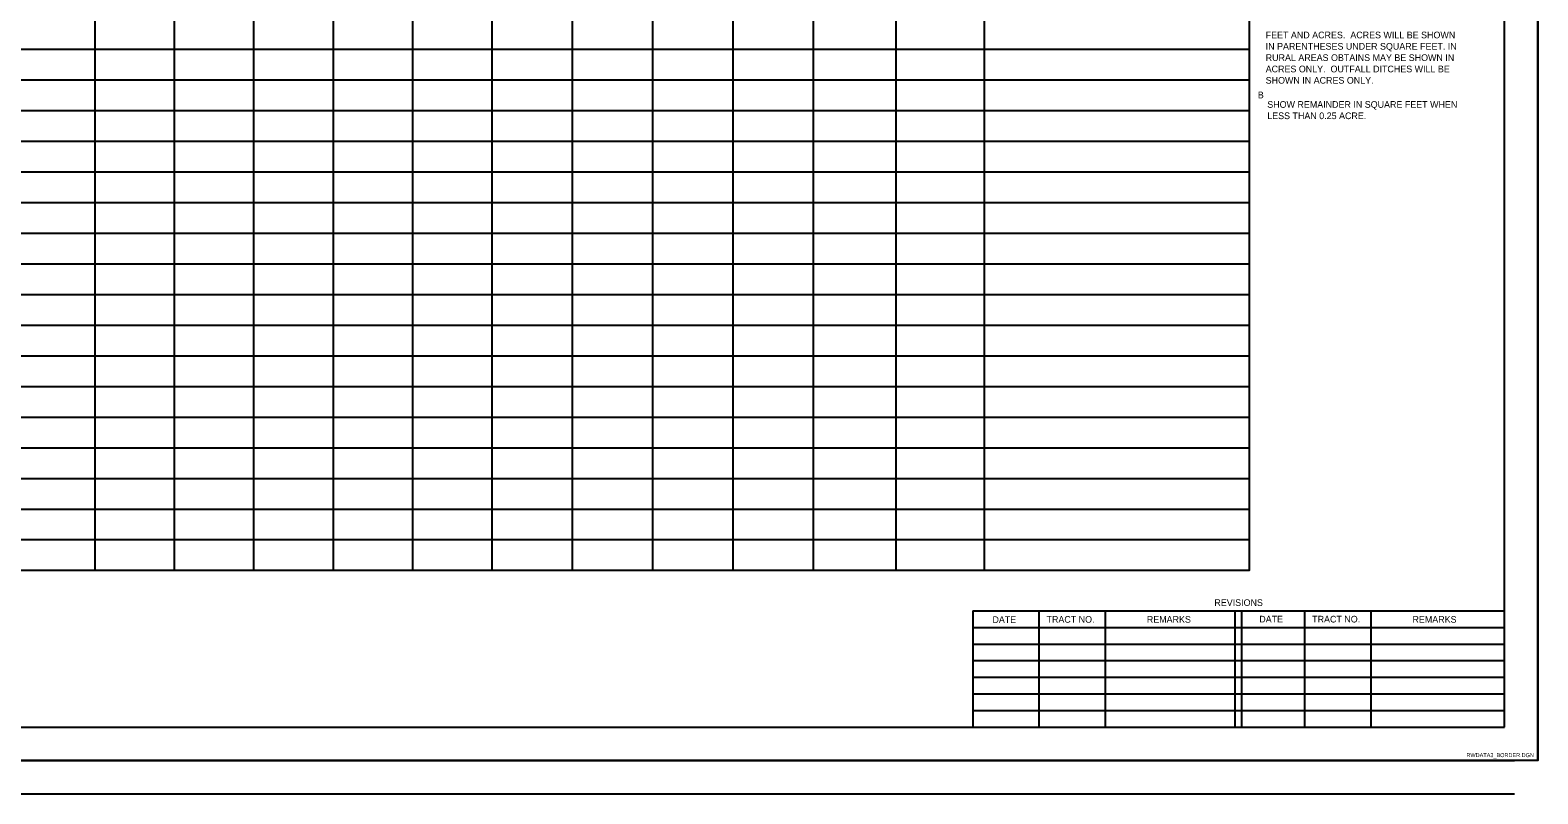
# Model space of a CAD drawing. Extents: x -19 to 1777, y -25 to 1125.
# Drawn here: x 646 to 1777, y -25 to 548 of the extents above; entities that cross this region are included whole.
import ezdxf

# ---------------------------------------------------------------- set-up
doc = ezdxf.new("R2010")
doc.units = 0
for name, color, linetype in [('RD_SHT_Bndy', 7, 'Continuous'), ('RD_SHT_Iplotshp', 7, 'Continuous'), ('RD_SHT_MjGrid', 7, 'Continuous'), ('RD_SHT_Snap', 7, 'Continuous'), ('RD_SHT_TX', 7, 'Continuous')]:
    doc.layers.add(name, color=color, linetype=linetype)

msp = doc.modelspace()

# ---------------------------------------------------------------- linework, layer by layer
at = {"layer": 'RD_SHT_Bndy'}
for p, q in [((1752.4, 25), (1752.4, 1075)), ((1353.4, 112.2), (1752.4, 112.2)), ((1353.4, 112.2), (1353.4, 25)), ((1402.9, 112.2), (1402.9, 25)), ((1452.7, 112.2), (1452.7, 25)), ((1549.9, 112.2), (1549.9, 25)), ((1554.9, 112.2), (1554.9, 25)), ((1602.3, 112.2), (1602.3, 25)), ((1652.1, 112.2), (1652.1, 25)), ((1353.4, 99.8), (1752.4, 99.8)), ((1353.4, 87.3), (1752.4, 87.3)), ((1353.4, 74.9), (1752.4, 74.9)), ((1353.4, 62.4), (1752.4, 62.4)), ((1353.4, 49.9), (1752.4, 49.9)), ((1353.4, 37.5), (1752.4, 37.5)), ((77.4, 25), (1752.4, 25)), ((0, 0), (1760, 0)), ((0, -25), (1760, -25))]:
    msp.add_line(p, q, dxfattribs=at)
msp.add_lwpolyline([(218, 142.7), (1560.9, 142.7), (1560.9, 996.8), (218, 996.8)], close=True, dxfattribs=at)
at = {"layer": 'RD_SHT_Iplotshp'}
msp.add_lwpolyline([(-18.6, 1100), (1777.4, 1100), (1777.4, 0), (-18.6, 0)], close=True, dxfattribs=at)
at = {"layer": 'RD_SHT_MjGrid'}
for p, q in [((813.7, 142.7), (813.7, 996.8)), ((873.3, 142.7), (873.3, 996.8)), ((932.9, 142.7), (932.9, 996.8)), ((992.6, 142.7), (992.6, 996.8)), ((1052.8, 142.7), (1052.8, 996.8)), ((1113.1, 142.7), (1113.1, 996.8)), ((1173.3, 142.7), (1173.3, 996.8)), ((1233.6, 142.7), (1233.6, 996.8)), ((1295.7, 142.7), (1295.7, 996.8)), ((1362.1, 142.7), (1362.1, 996.8)), ((1560.9, 142.7), (1560.9, 996.8)), ((694.4, 142.7), (694.4, 974.4)), ((754, 142.7), (754, 974.4)), ((218, 533.4), (1560.9, 533.4)), ((218, 510.4), (1560.9, 510.4)), ((218, 487.4), (1560.9, 487.4)), ((218, 464.4), (1560.9, 464.4)), ((218, 441.4), (1560.9, 441.4)), ((218, 418.5), (1560.9, 418.5)), ((218, 395.5), (1560.9, 395.5)), ((218, 372.5), (1560.9, 372.5)), ((218, 349.5), (1560.9, 349.5)), ((218, 326.5), (1560.9, 326.5)), ((218, 303.6), (1560.9, 303.6)), ((218, 280.6), (1560.9, 280.6)), ((218, 257.6), (1560.9, 257.6)), ((218, 234.6), (1560.9, 234.6)), ((218, 211.6), (1560.9, 211.6)), ((218, 188.6), (1560.9, 188.6)), ((218, 165.7), (1560.9, 165.7)), ((218, 142.7), (1560.9, 142.7))]:
    msp.add_line(p, q, dxfattribs=at)
at = {"layer": 'RD_SHT_Snap'}
msp.add_line((1777.4, 0), (1777.4, 1100), dxfattribs=at)

# ---------------------------------------------------------------- texts
at = {"layer": 'RD_SHT_TX'}
for s, height, p in [('FEET AND ACRES.  ACRES WILL BE SHOWN ', 5, (1573.1, 541.6)), ('IN PARENTHESES UNDER SQUARE FEET. IN ', 5, (1573.1, 533.1)), ('ACRES ONLY.  OUTFALL DITCHES WILL BE', 5, (1573.1, 516.1)), ('RURAL AREAS OBTAINS MAY BE SHOWN IN', 5, (1573.1, 524.6)), ('SHOWN IN ACRES ONLY.', 5, (1573.1, 507.6)), ('B', 5, (1567.2, 496.6)), ('SHOW REMAINDER IN SQUARE FEET WHEN ', 5, (1574.3, 489.5)), ('LESS THAN 0.25 ACRE.', 5, (1574.3, 481)), ('REVISIONS', 5, (1534.6, 115.9)), ('DATE', 5, (1368, 103.1)), ('TRACT NO.', 5, (1408.6, 103.3)), ('REMARKS', 5, (1483.9, 103.3)), ('DATE', 5, (1568.3, 103.5)), ('TRACT NO.', 5, (1608, 103.5)), ('REMARKS', 5, (1683.3, 103.3)), ('RWDATA3_BORDER.DGN', 3, (1723.8, 2.5))]:
    msp.add_text(s, height=height, dxfattribs=at).set_placement(p)

doc.saveas('drawing.dxf')
